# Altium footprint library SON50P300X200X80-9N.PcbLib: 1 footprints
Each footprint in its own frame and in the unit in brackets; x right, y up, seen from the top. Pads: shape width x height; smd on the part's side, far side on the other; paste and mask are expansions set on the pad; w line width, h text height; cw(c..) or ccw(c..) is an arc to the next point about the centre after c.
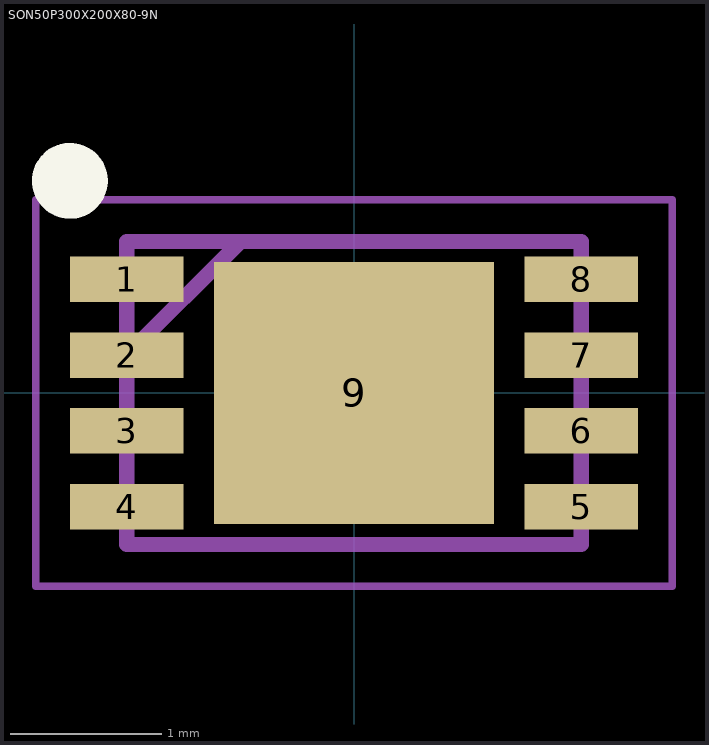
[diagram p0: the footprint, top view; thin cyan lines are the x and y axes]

## SON50P300X200X80-9N [mm]
pads (9):
  rect 0.75x0.3 smd: 1(-1.5,0.75) 2(-1.5,0.25) 3(-1.5,-0.25) 4(-1.5,-0.75) 5(1.5,-0.75) 6(1.5,-0.25) 7(1.5,0.25) 8(1.5,0.75)
  rect 1.85x1.73 smd: 9(0,0)
Top Overlay:
  circle w0.25: c-1.875,1.4 r0.125
Mechanical 15:
  lines w0.1: -1.5,0.25 -0.75,1 ; -1.5,-1 1.5,-1 1.5,1 -1.5,1 -1.5,-1
Mechanical 20:
  lines w0.05: -2.1,-1.275 2.1,-1.275 2.1,1.275 -2.1,1.275 -2.1,-1.275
